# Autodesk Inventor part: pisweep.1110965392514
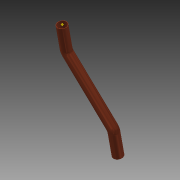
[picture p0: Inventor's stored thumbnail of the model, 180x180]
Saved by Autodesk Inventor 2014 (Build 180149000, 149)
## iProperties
TPVersion: 11.0.2
Company: Autodesk, Inc.
Created: 2005-03
Material: Copper
Description: Tube
Document SubType Name: Modeling
Designer: Autodesk, Inc.
Stock Number: ASTM B 88 Tube 2 - Type L
Categories: <pipe>
Density: 1 g/cm^3
Appearance: Copper - Satin
PL: 27.612 in
OD: 1.063 in
ID: 0.993 in
Author: Autodesk, Inc.
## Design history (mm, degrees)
sketch "3D Sketch2" dims "d3" = 50.7999, "d4" = 50.7999
workpoint "Work Point6"
workpoint "Work Point7"
workpoint "Work Point8"
workpoint "Work Point9"
workplane "Work Plane2"
sketch "Sketch2"
  geometry: C1 r 26.988 at (0, 0); C2 r 25.209 at (0, 0); 1 further point
  constraints: 2 centre point
workpoint "Work Point10"
sweep "Sweep2" dims "d5" = 0
body "Solid1"
other parameters: "PL" = 701.3448 [user parameter], "OD" = 26.9875 [user parameter], "ID" = 25.2095 [user parameter]
